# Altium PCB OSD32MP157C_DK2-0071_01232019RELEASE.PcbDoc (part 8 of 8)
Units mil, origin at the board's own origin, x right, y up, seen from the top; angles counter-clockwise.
Board outline 3976.38 x 2795.28 mil, 6 copper layers (Top Layer, Signal Layer 1, Signal Layer 2, Signal Layer 3, Signal Layer 4, Bottom Layer), stack 61.268 mil thick; 404 components, 418 nets, 1720 pads, 1233 vias.
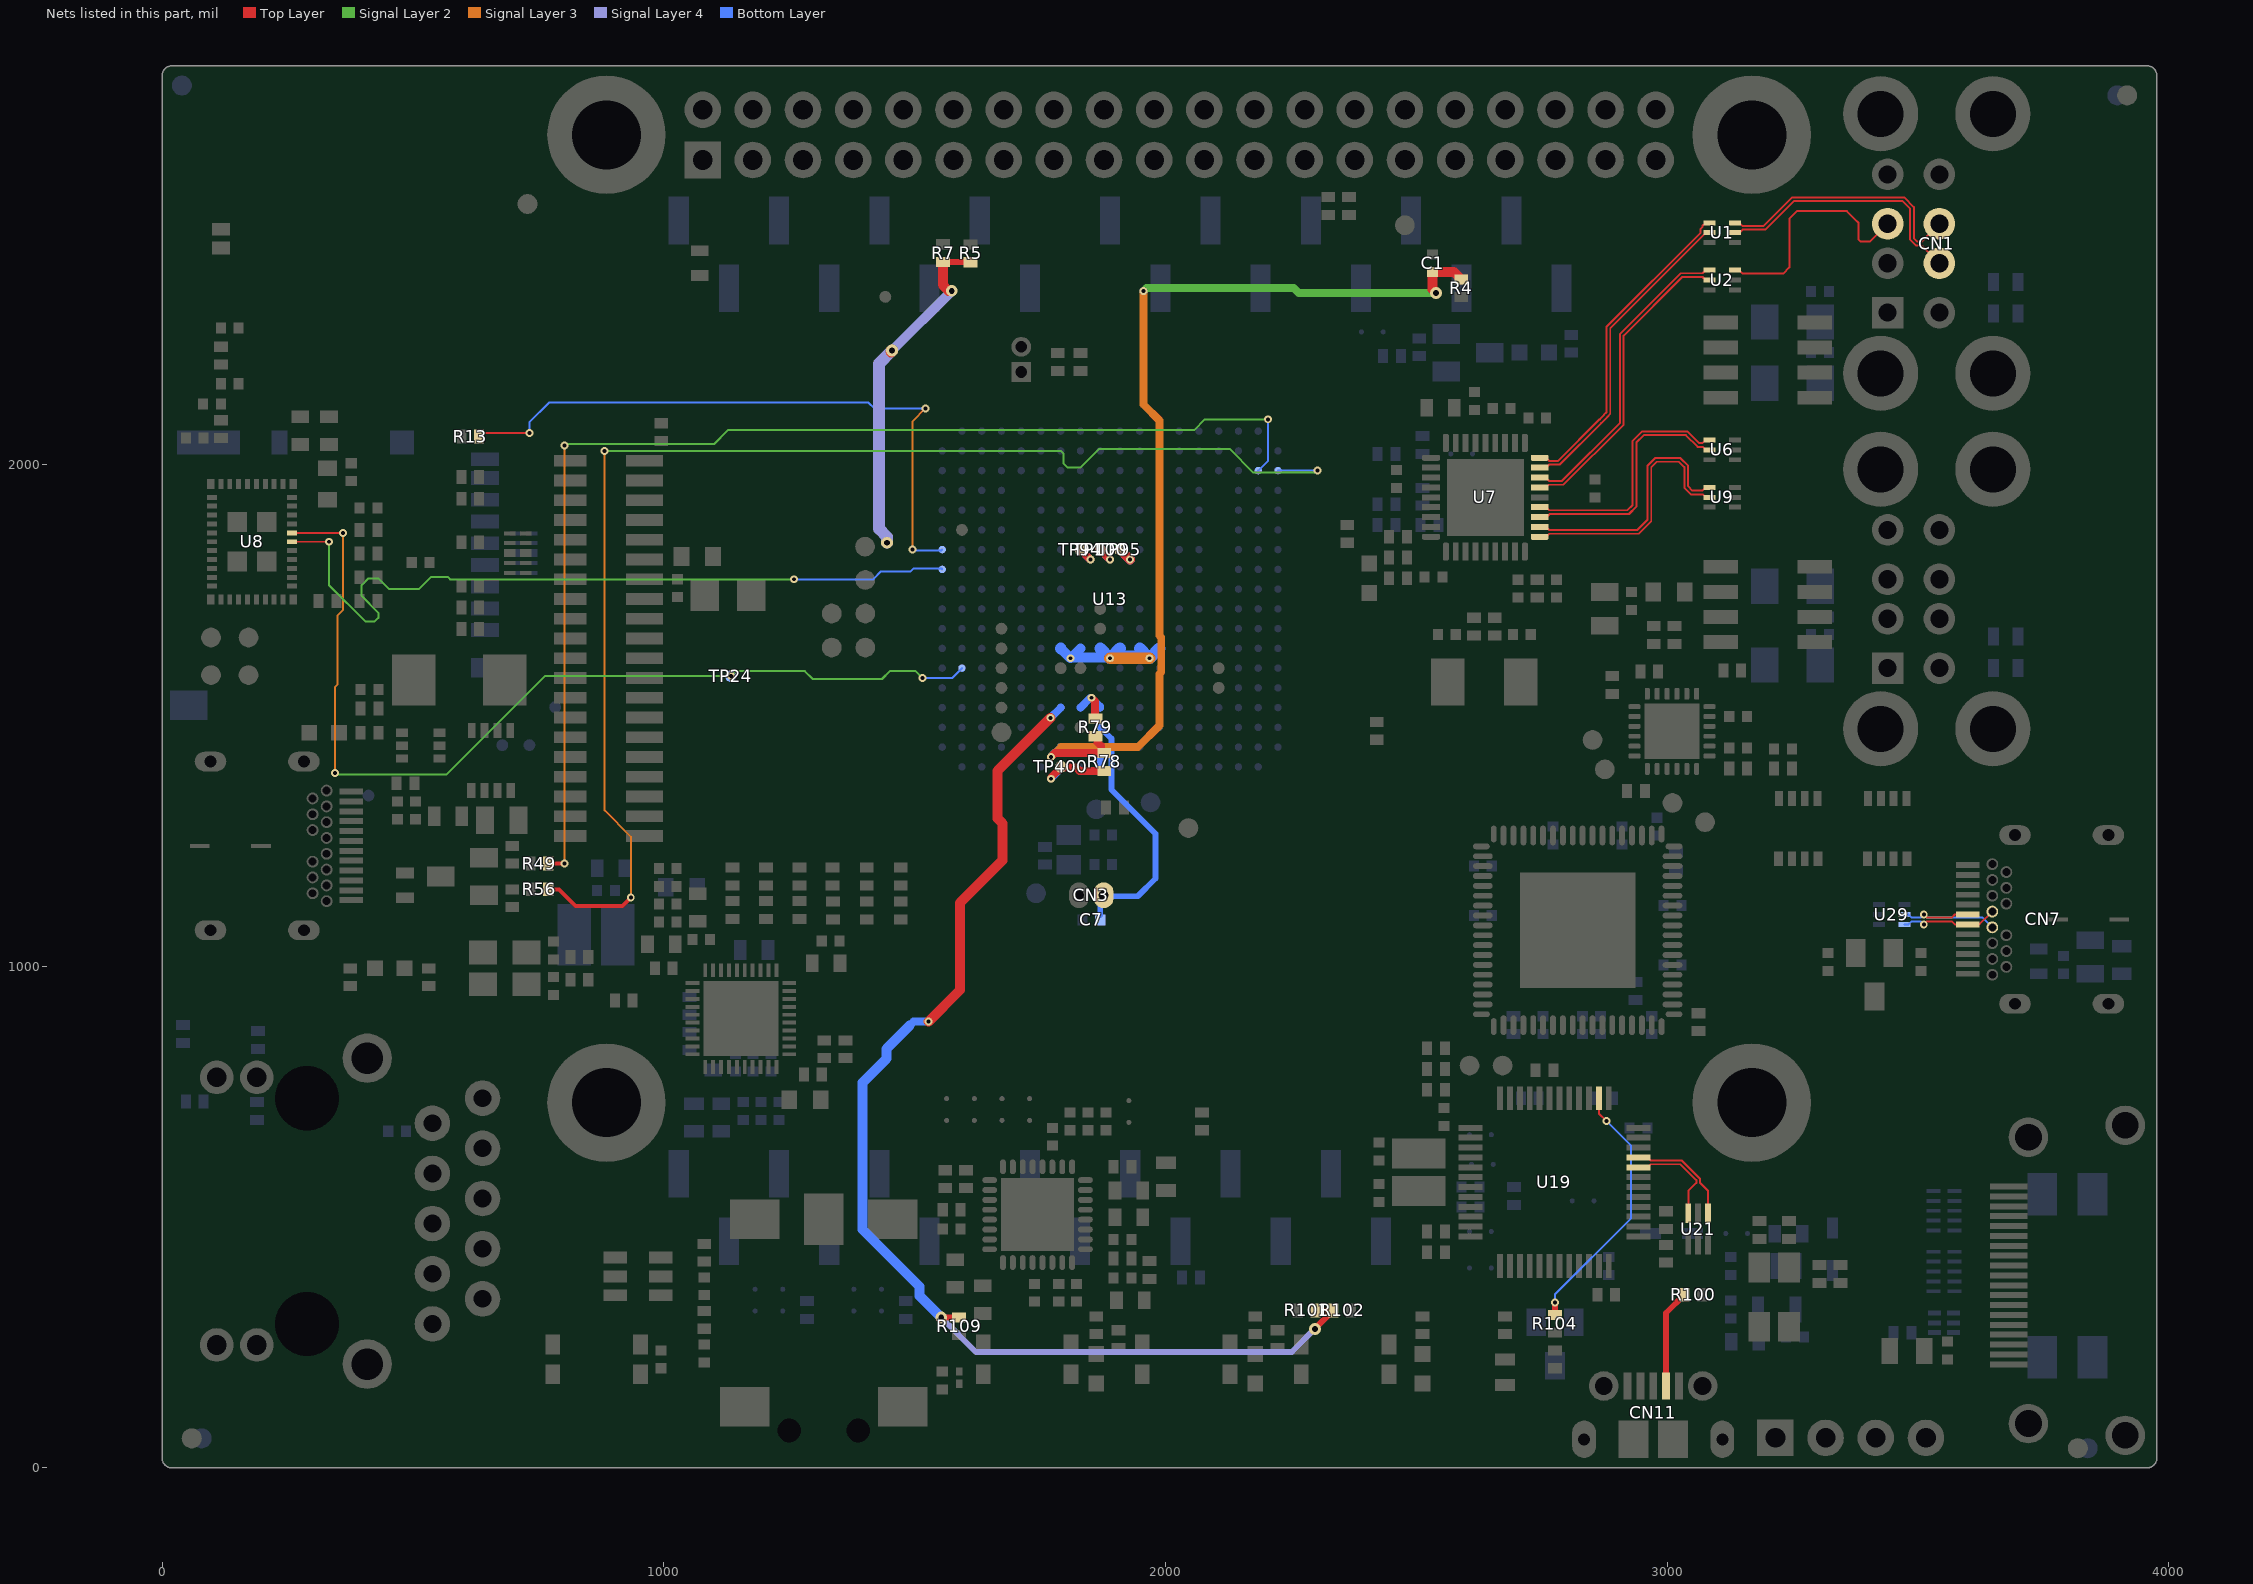
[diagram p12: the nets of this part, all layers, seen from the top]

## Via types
v1: diameter 15.75, hole 7.87, Top Layer to Bottom Layer, tented both sides, 803 vias
v2: diameter 23.62, hole 11.81, Top Layer to Bottom Layer, tented both sides, 417 vias
v3: diameter 15.75, hole 7.87, Top Layer to Bottom Layer, 13 vias

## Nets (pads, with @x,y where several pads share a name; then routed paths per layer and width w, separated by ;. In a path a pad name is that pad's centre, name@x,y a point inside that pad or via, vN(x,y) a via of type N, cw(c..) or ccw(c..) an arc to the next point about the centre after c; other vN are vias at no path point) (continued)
USB3CN26_P: CN1.T3 U2.6 | length 474.8
  Top Layer w3.94: U2.6@3135.83,2387.8 3143.7,2387.8 3150.59,2380.91 3231.3,2380.91 3243.92,2393.53 3243.92,2490.72 3258.71,2505.51 3358.41,2505.51 3379.31,2484.62 3381.5,2482.43 3381.5,2449.21 3386.02,2444.68 3404.13,2444.68 CN1.T3@3439.76,2480.31
USB4CN26_N: CN1.B2 U1.5 | length 520.8
  Top Layer w3.94: U1.5@3135.83,2462.6 3144.68,2462.6 3150.59,2468.5 3195.87,2468.5 3252.95,2525.59 3469.49,2525.59 3484.65,2510.43 3484.65,2448.48 3495.92,2437.2 3507.28,2437.2 CN1.B2@3542.91,2401.57
USB4CN26_P: CN1.B3 U1.6 | length 521
  Top Layer w3.94: U1.6@3135.83,2482.28 3143.7,2482.28 3150,2475.98 3192.77,2475.98 3249.85,2533.07 3472.59,2533.07 3492.13,2513.53 3492.13,2451.57 3499.02,2444.68 3507.28,2444.68 CN1.B3@3542.91,2480.31
USB_DCONN_N: CN7.A7 CN7.B7 U29.5 | length 283.1
  Top Layer w3.94: v1(3511.81,1103.35) 3517.91,1097.24 3567.52,1097.24 3573.62,1103.35 CN7.A7@3599.21,1103.35
  Bottom Layer w3.94: U29.5@3473.43,1103.35 3481.3,1103.35 3487.4,1097.24 3505.71,1097.24 v1(3511.81,1103.35) 3517.91,1097.24 3628.94,1097.24 CN7.B7@3648.43,1077.76
USB_DCONN_P: CN7.A6 CN7.B6 U29.6 | length 195.7
  Top Layer w3.94: v1(3511.81,1083.66) 3517.91,1089.76 3567.52,1089.76 3573.62,1083.66 CN7.A6@3599.21,1083.66 3622.83,1083.66 CN7.B6@3648.43,1109.25
  Bottom Layer w3.94: U29.6@3473.43,1083.66 3481.3,1083.66 3487.4,1089.76 3505.71,1089.76 v1(3511.81,1083.66)
USB_PWR_CC1: R49.2 U13.B16 | length 2400.8
  Top Layer w7.87: R49.2@769.68,1204.72 v1(802.17,1204.72)
  Signal Layer 2 w3.94: v1(802.17,2038.39) 805.12,2041.34 1100.39,2041.34 1127.95,2068.9 2057.09,2068.9 2078.74,2090.55 v1(2204.72,2090.55)
  Signal Layer 3 w3.94: v1(802.17,1204.72) v1(802.17,2038.39)
  Bottom Layer w3.94: U13.B16@2185.04,1988.19 2204.72,2007.87 v1(2204.72,2090.55)
USB_PWR_CC2: R56.2 U13.A16 | length 2662.9
  Top Layer w7.87: R56.2@769.68,1153.54 791.14,1153.54 824.02,1120.67 917.52,1120.67 v1(934.25,1137.4)
  Signal Layer 2 w3.94: v1(881.89,2027.56) 1169.09,2027.56 ; 1169.09,2027.56 1791.34,2027.56 1797.24,2021.65 1797.24,2002.17 1805.32,1994.09 1830.65,1994.09 1868.05,2031.5 2127.95,2031.5 2175.2,1984.25 2299.21,1984.25 v1(2303.15,1988.19)
  Signal Layer 3 w3.94: v1@881.89,2031.5 881.89,1311.02 934.25,1258.66 v1(934.25,1137.4)
  Bottom Layer w3.94: U13.A16@2224.41,1988.19 v1(2303.15,1988.19)
USB_RENUMN: R104.2 U19.38 | length 521.5
  Top Layer w3.94: U19.38@2864.17,737.2 2864.17,706.69 v1(2878.94,691.93)
  Top Layer w11.81: R104.2@2776.57,305.12 v1(2776.57,329.72)
  Bottom Layer w3.94: v1(2776.57,329.72) 2776.57,345.87 2928.35,497.64 2928.35,642.52 v1(2878.94,691.93)
USB_STLK_ID: CN11.4 R100.2 | length 197.2
  Top Layer w11.81: CN11.4@2998.03,163.39 2998.03,309.06 R100.2@3034.45,345.47
USB_STLK_N: U19.32 U21.6 | length 203.4
  Top Layer w3.94: U19.32@2942.91,599.41 2961.61,599.41 2967.72,605.51 3026.63,605.51 3058.27,573.87 3058.27,572.54 3058.27,569.89 3058.27,568.56 3042.32,552.61 U21.6@3042.32,508.07
USB_STLK_P: U19.33 U21.4 | length 215.8
  Top Layer w3.94: U19.33@2942.91,619.09 2961.61,619.09 2967.72,612.99 3029.72,612.99 3065.75,576.97 3065.75,568.56 3081.69,552.61 U21.4@3081.69,508.07
USBDN1_N: U7.1 U9.2 | length 517.3
  Top Layer w3.94: U7.1@2746.06,1856.3 2758.86,1856.3 2764.96,1862.4 2943.85,1862.4 2968.5,1887.06 2968.5,1995.08 2979.33,2005.91 3023.62,2005.91 3034.45,1995.08 3034.45,1953.99 3047.49,1940.94 3070.87,1940.94 3076.77,1935.04 U9.2@3084.65,1935.04
USBDN1_P: U7.2 U9.1 | length 517.4
  Top Layer w3.94: U7.2@2746.06,1875.98 2758.86,1875.98 2764.96,1869.88 2940.75,1869.88 2961.02,1890.16 2961.02,1998.18 2976.23,2013.39 3026.72,2013.39 3041.93,1998.18 3041.93,1957.09 3050.59,1948.43 3070.47,1948.43 3076.77,1954.72 U9.1@3084.65,1954.72
USBDN2_N: U6.2 U7.3 | length 493.3
  Top Layer w3.94: U7.3@2746.06,1895.67 2759.84,1895.67 2765.94,1901.77 2924.16,1901.77 2938.98,1916.59 2938.98,2044.29 2953.74,2059.06 3037.4,2059.06 3061.02,2035.43 3070.87,2035.43 3076.77,2029.53 U6.2@3084.65,2029.53
USBDN2_P: U6.1 U7.4 | length 493.5
  Top Layer w3.94: U7.4@2746.06,1915.35 2758.86,1915.35 2764.96,1909.25 2921.06,1909.25 2931.5,1919.69 2931.5,2047.39 2950.64,2066.54 3040.5,2066.54 3064.12,2042.91 3070.47,2042.91 3076.77,2049.21 U6.1@3084.65,2049.21
USBDN3_N: U2.2 U7.6 | length 618.6
  Top Layer w3.94: U7.6@2746.06,1954.72 2758.86,1954.72 2764.17,1960.04 2793.45,1960.04 2913.39,2079.97 2913.39,2257.14 3030.46,2374.21 3070.67,2374.21 3076.77,2368.11 U2.2@3084.65,2368.11
USBDN3_P: U2.1 U7.7 | length 619.3
  Top Layer w3.94: U7.7@2746.06,1974.41 2757.87,1974.41 2764.76,1967.52 2790.35,1967.52 2905.91,2083.07 2905.91,2260.24 3027.36,2381.69 3070.67,2381.69 3076.77,2387.8 U2.1@3084.65,2387.8
USBDN4_N: U1.2 U7.8 | length 632.8
  Top Layer w3.94: U7.8@2746.06,1994.09 2758.86,1994.09 2765.16,2000.39 2785.83,2000.39 2868.5,2083.07 2869.04,2083.07 2881.5,2095.52 2881.5,2096.06 2886.81,2101.38 2886.81,2271.9 3077.51,2462.6 U1.2@3084.65,2462.6
USBDN4_P: U1.1 U7.9 | length 643.5
  Top Layer w3.94: U7.9@2746.06,2013.78 2758.86,2013.78 2764.76,2007.87 2782.73,2007.87 2865.41,2090.55 2865.94,2090.55 2874.02,2098.62 2874.02,2099.16 2879.33,2104.48 2879.33,2275 3066.93,2462.6 3066.93,2469.97 3070.39,2473.43 3070.39,2475.9 3076.77,2482.28 U1.1@3084.65,2482.28
USD_DETECT: R13.1 U13.V12 | length 1288.3
  Top Layer w3.94: R13.1@631.89,2056.1 638.78,2062.99 v1(732.28,2062.99)
  Signal Layer 3 w3.94: v1(1496.06,1830.71) 1496.06,2086.61 v1(1521.65,2112.2)
  Bottom Layer w3.94: v1(732.28,2062.99) 732.28,2084.65 771.65,2124.02 1407.48,2124.02 1419.29,2112.2 v1(1521.65,2112.2) ; v1(1496.06,1830.71) 1498.03,1828.74 1553.15,1828.74 U13.V12@1555.12,1830.71
VBAT: C7.2 CN3.1 U13.K3 | length 507.9
  Bottom Layer w11.81: C7.2@1870.08,1102.36 1870.08,1134.84 CN3.1@1876.97,1141.73 1878.94,1139.76 1944.88,1139.76 1980.31,1175.2 1980.31,1264.32 1892.22,1352.41 1892.22,1454.23 U13.K3@1870.08,1476.38
VDD: R5.1 R7.1 R79.1 R101.2 R102.2 R109.2 U13.G7 U13.H7 U13.J7 U13.K4 U13.K7 U13.L4 U13.L7 U13.M4 U13.M7 | length 3576.9
  Top Layer w11.81: v2(1553.15,300.2) R109.2@1588.58,300.2 ; R7.1@1556.89,2404.13 R5.1@1611.02,2404.13 ; v2(2297.93,277.26) R102.2@2334.65,313.98 R101.2@2299.21,313.98
  Top Layer w15.75: v1(1852.36,1535.43) 1860.03,1527.76 1860.03,1494.46 R79.1@1860.39,1494.1
  Top Layer w19.68: R7.1@1556.89,2404.13 1556.89,2357.68 1567.92,2346.65 v2(1574.02,2346.65)
  Top Layer w20: v3(1527.56,889.76) 1590.55,952.76 1590.55,1126.63 1675.35,1211.44 1675.35,1285.03 1665.2,1295.19 1665.2,1389.76 1770.92,1495.49 v1(1771.08,1495.49)
  Top Layer w23.62: v2@1453.35,2225.98 v2(1454.72,2227.36)
  Signal Layer 3 w7.87: v2(1454.72,2227.36) 1454.72,2229.36 v2@1455.68,2230.31
  Signal Layer 3 w23.62: v1(1889.76,1614.17) v1(1968.5,1614.17)
  Signal Layer 4 w11.81: v2(1553.15,300.2) 1622.05,231.3 2251.97,231.3 v2(2297.93,277.26)
  Signal Layer 4 w19.68: v2@1454.63,2226.87 1454.63,2227.26 v2(1454.72,2227.36) v2(1574.02,2346.65)
  Signal Layer 4 w23.62: v2(1444.88,1844.49) 1444.88,1856.3 1429.13,1872.05 1429.13,2201.77 v2@1454.63,2227.26
  Bottom Layer w15.75: 1490.16,881.89 1498.03,889.76 v3(1527.56,889.76) ; v1(1771.08,1495.49) U13.M4@1791.34,1515.75 ; U13.L4@1830.71,1515.75 1850.39,1535.43 v1(1852.36,1535.43) 1870.08,1517.71 U13.K4@1870.08,1515.75
  Bottom Layer w19.68: U13.M7@1791.34,1633.86 v1(1811.02,1614.17) v1@1812.5,1615.65 ; U13.L7@1830.71,1633.86 v1@1812.5,1615.65 ; v1(1889.76,1614.17) 1888.29,1615.65 v1@1812.5,1615.65
  Bottom Layer w20: 1490.16,881.89 1443.9,835.63 1443.9,815.94 1395.98,768.03 1395.98,475.67 1510,361.66 1510,343.35 v2(1553.15,300.2)
  Bottom Layer w23.62: U13.K7@1870.08,1633.86 v1@1888.29,1615.65 ; v1(1889.76,1614.17) v1@1893.21,1617.62 ; U13.J7@1909.45,1633.86 v1@1893.21,1617.62 ; U13.H7@1948.82,1633.86 v1@1965.06,1617.62 ; U13.G7@1988.19,1633.86 v1(1968.5,1614.17) v1@1965.06,1617.62 ; v1@1893.21,1617.62 v1@1965.06,1617.62
VDD_DDR: TP100.1 U13.K12 | length 55.7
  Top Layer w15.75: TP100.1@1870.08,1830.71 v1(1889.76,1811.02)
  Bottom Layer w15.75: U13.K12@1870.08,1830.71 v1(1889.76,1811.02)
VDDA: R78.1 TP400.1 U13.M1 | length 150.9
  Top Layer w15.75: v1(1771.65,1374.01) 1771.65,1375.82 1791.96,1396.13 1822.53,1396.13 1828.89,1389.77 R78.1@1877.95,1389.77
  Bottom Layer w15.75: v1(1771.65,1374.01) 1791.34,1393.7 U13.M1@1791.34,1397.64
VREF+: C1.2 R4.2 R78.2 R79.2 U13.M2 | length 2012.8
  Top Layer w15.75: v1(1771.65,1417.32) 1779.53,1425.2 R78.2@1874.21,1425.2 ; R79.2@1862.56,1460.83 R79.2@1860.39,1458.67 1864.13,1458.67 1864.13,1446.89 1872.05,1438.98 1872.05,1427.37 R78.2@1874.21,1425.2 ; R78.2@1880.86,1424.12 R78.2@1877.95,1427.02 ; R78.2@1874.21,1425.2 R78.2@1875.45,1425.2 ; R78.2@1875.45,1425.2 1877.61,1427.37 R78.2@1877.95,1427.02 ; R78.2@1875.45,1425.2 R78.2@1877.95,1425.2 R78.2@1877.95,1427.02
  Top Layer w19.68: v2(2539.37,2342.52) 2532.48,2349.41 C1.2@2532.48,2383.86 2575.59,2383.86 R4.2@2589.92,2369.53
  Signal Layer 2 w15.75: v3(1956.69,2346.45) 1962.6,2352.36 2058.77,2352.36 ; 2058.77,2352.36 2075.08,2352.36 ; 2075.08,2352.36 2255.91,2352.36 2265.75,2342.52 v2(2539.37,2342.52)
  Signal Layer 3 w15.75: v1(1771.65,1417.32) 1791.34,1437.01 1944.88,1437.01 1988.19,1480.31 1988.19,1582.96 1991.73,1586.5 1991.73,1655.91 1988.19,1659.45 1988.19,2088.3 1956.69,2119.8 v3(1956.69,2346.45)
  Bottom Layer w15.75: v1(1771.65,1417.32) U13.M2@1791.34,1437.01
VREF_DDR: TP94.1 U13.L12 | length 55.7
  Top Layer w15.75: TP94.1@1830.71,1830.71 v1(1850.39,1811.02)
  Bottom Layer w15.75: U13.L12@1830.71,1830.71 v1(1850.39,1811.02)
VSSA: U13.K1 U13.K2 | length 39.4
  Bottom Layer w15.75: U13.K1@1870.08,1397.64 U13.K2@1870.08,1437.01
VTT_DDR: TP95.1 U13.J12 | length 55.7
  Top Layer w19.68: TP95.1@1909.45,1830.71 v1(1929.13,1811.02)
  Bottom Layer w19.68: U13.J12@1909.45,1830.71 v1(1929.13,1811.02)
WL_HOST_WAKE: U8.27 U13.V11 | length 1566.4
  Top Layer w3.94: U8.27@258.86,1846.46 v1(332.68,1846.46)
  Signal Layer 2 w3.94: v1(332.68,1846.46) 332.68,1759.84 405.51,1687.01 423.23,1687.01 431.1,1694.88 431.1,1704.84 397.67,1738.27 397.67,1759.88 411.42,1773.62 431.1,1773.62 452.76,1751.97 511.81,1751.97 536.42,1776.57 569.35,1776.57 574.27,1771.65 v1(1259.84,1771.65)
  Bottom Layer w3.94: v1(1259.84,1771.65) 1417.32,1771.65 1433.07,1787.4 1492.13,1787.4 1498.03,1793.31 1555.12,1793.31 U13.V11@1555.12,1791.34
WL_REG_ON: TP24.1 U8.28 U13.U6 | length 1949.6
  Top Layer w3.94: U8.28@258.86,1864.17 v1(360.24,1864.17)
  Signal Layer 2 w3.94: v1(344.49,1385.83) 347.44,1382.87 566.93,1382.87 762.8,1578.74 v1(1133.86,1578.74) 1143.7,1588.58 1281.5,1588.58 1297.24,1572.83 1435.04,1572.83 1450.79,1588.58 1501.97,1588.58 v1(1515.75,1574.8)
  Signal Layer 3 w3.94: v1(344.49,1385.83) 344.49,1556.55 349.41,1561.47 349.41,1699.27 360.24,1710.09 v1(360.24,1864.17)
  Bottom Layer w3.94: v1(1515.75,1574.8) 1574.8,1574.8 U13.U6@1594.49,1594.49
pads on no net: CN6.0 CN6.A2 CN6.A3 CN6.A6 CN6.A7 CN6.A8 CN6.A10 CN6.A11 CN6.B2 CN6.B3 CN6.B6 CN6.B7 CN6.B8 CN6.B10 CN6.B11 CN7.0 CN7.A2 CN7.A3 CN7.A8 CN7.A10 CN7.A11 CN7.B2 CN7.B3 CN7.B8 CN7.B10 CN7.B11 CN8.17 CN8.18 CN9.14 CN10.NPTH1 CN10.NPTH2 CN16.1 CN16.8 L1.2 U1.4 U2.4 U6.4 U8.13 U8.15 U8.16 U9.4 U10.4 U10.5 U10.6 U10.7 U12.16 U12.17 U12.19 U13.D7 U13.D8 U13.D9 U13.D10 U13.G8 U13.H12 U13.M16 U13.P9 U13.P10 U13.R9 U13.R10 U14.36 U14.37 U14.38 U14.39 U14.40 U19.4 U19.11 U19.14 U19.16 U19.17 U19.19 U19.21 U19.22 U19.28 U19.29 U19.40 U19.41 U19.42 U19.43 U19.45 U19.46 U20.19 U20.20 U20.23 U20.24 U29.4 U33.5 X2.2 X2.4
copper on no net: | length 33.5
  Bottom Layer w11.81: v2(2990.16,705.71) 2990.16,739.17
  other v2: 1043.31,2256.89 1043.31,2315.94

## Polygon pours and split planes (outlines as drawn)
GND on Bottom Layer "GND_L06_P130" (solid, remove dead copper, pour order 130): 89.45,2820.55 1752.83,2820.55 2301.65,2820.55 4065.83,2820.55 4065.83,25.28 89.45,25.28
GND on Bottom Layer "GND_L06_P134" (solid, remove dead copper, pour order 134): 1604.33,2795.28 1604.33,2312.99 2340.06,2312.99 2340.06,2795.28
NetC69_2 on Bottom Layer "NETC69_2_L06_P097" (solid, remove dead copper, pour order 97): 319.88,1300.2 311.81,1292.12 311.81,1186.23 322.11,1175.91 539.1,1175.91 556.1,1192.91 556.1,1288.39 544.29,1300.2
3V3 on Signal Layer 4 "3V3_L05_P113" (solid, remove dead copper, pour order 113): 1952.12,2635.43 1934.06,2617.37 1934.06,2570.87 1916.34,2553.15 1839.57,2553.15 1817.91,2574.8 1817.91,2624.2 1806.68,2635.43 1146.62,2635.43 1134.8,2621.62 1134.8,2566.88 1117.13,2549.21 1011.42,2549.21 859.45,2397.24 859.45,2212.2 977.56,2094.09 977.56,2074.41 967.72,2064.57 957.87,2064.57 898.82,2005.51 898.82,1966.54 583.86,1651.57 583.86,1533.07 524.8,1474.02 416.54,1474.02 396.85,1454.33 396.85,1414.96 485.43,1326.38 652.76,1326.38 731.5,1405.12 826.77,1405.12 1066.14,1644.49 1066.14,1769.29 1125.2,1828.35 1125.2,1867.72 1144.88,1887.4 1144.88,1926.77 1135.04,1936.61 1095.67,1936.61 1085.83,1946.46 1085.83,1966.14 1095.67,1975.98 2224.41,1975.98 2224.41,598.61 1115.35,598.03 997.24,479.92 997.24,283.07 1026.77,253.54 1479.53,253.54 1538.58,194.49 1853.54,194.49 1873.23,174.8 2335.83,174.8 2365.35,204.33 2365.35,322.44 2375.2,332.28 2493.31,332.28 2522.83,302.76 2522.83,26.77 2496.06,0 3.15,0 3.15,1705.71 381.69,2084.25 603.54,2084.25 633.07,2113.78 633.07,2743.7 682.28,2792.91 3034.65,2792.91 3034.65,2694.49 3005.12,2664.96 2847.64,2664.96 2818.11,2635.43
GND on Signal Layer 4 "GND_L05_P144" (solid, remove dead copper, pour order 144): 1308.87,1023.62 2401.57,1023.62 2401.57,2422.42 1308.87,2422.43
3V3 on Signal Layer 4 "3V3_L05_P117" (solid, remove dead copper, pour order 117): 2881.53,2409.06 2936.22,2354.37 2936.22,1641.34 2562.21,1267.32 2562.2,991.73 2601.57,952.36 2601.57,706.3 2601.57,499.61 2522.83,420.87 2460.63,420.87 2460.63,342.13 2483.46,342.13 2493.31,332.28 2463.78,302.76 2385.63,302.76 2375.45,292.58 2365.69,292.58 2355.51,302.76 2325.98,302.76 2266.93,243.7 1935.04,243.7 1925.2,253.54 1824.02,253.54 1814.17,263.39 1814.17,308.07 1828.54,322.44 1961.81,322.44 1971.65,312.6 2011.02,312.6 2020.87,322.44 2020.87,607.87 1892.91,735.83 1873.23,735.83 1863.39,745.67 1863.39,785.04 1873.23,794.88 2208.07,794.88 2227.56,775.39 2227.56,735.83 2247.24,716.14 2365.35,716.14 2385.04,735.83 2385.04,863.78 2385.04,942.52 2375.2,952.36 2296.46,1031.1 2296.46,1139.37 2424.41,1267.32 2424.41,2369.69 2463.78,2409.06
AGND on Signal Layer 4 "AGND_L05_P109" (solid, remove dead copper, pour order 109): 1135.04,578.35 1016.93,460.24 1016.93,291.14 1034.84,273.23 1429.72,273.23 1504.53,348.03 1542.52,348.03 1614.96,275.59 1782.68,275.59 1804.33,297.24 1804.33,321.85 1814.76,332.28 1964.57,332.28 1974.41,322.44 2001.18,322.44 2011.02,332.28 2011.02,603.15 1891.73,722.44 1613.78,722.44 1607.48,716.14 1607.48,647.24 1538.58,578.35
5V_VIN on Signal Layer 4 "5V_VIN_L05_P090" (solid, remove dead copper, pour order 90): 2263.78,1338.58 2263.78,1484.8 1940.4,1484.8 1940.4,1338.58
5V_VIN on Signal Layer 4 "5V_VIN_L05_P112" (solid, remove dead copper, pour order 112): 2878.35,2428.74 2958.66,2348.43 2989.17,2348.43 3024.61,2383.86 3024.61,2625.79 3005.42,2644.97 2893.7,2645.28 2857.48,2645.28 2827.95,2615.75 1952.76,2615.75 1940.06,2602.46 1940.06,2567.03 1919.29,2546.26 1834.65,2546.26 1810.65,2570.26 1810.65,2598.41 1793.31,2615.75 1282.48,2615.75 1260.83,2637.8 1233.46,2637.8 1233.46,2723.23 1223.43,2733.27 1068.9,2733.27 1047.24,2711.61 1047.24,2644.98 1056.4,2635.83 1118.11,2635.83 1140.95,2612.99 1140.95,2573.04 1105.51,2537.6 1027.36,2537.6 879.13,2389.37 879.13,2202.36 987.4,2094.09 987.4,2074.41 918.5,2005.51 918.5,1956.3 603.54,1641.34 603.54,1530.51 527.36,1454.33 426.38,1454.33 416.54,1444.49 416.54,1424.8 495.28,1346.06 642.91,1346.06 721.65,1424.8 820.08,1424.8 1047.24,1651.97 1047.24,1770.08 1115.35,1838.19 1115.35,1877.56 1125.2,1887.4 1125.2,1916.93 1115.35,1926.77 1085.83,1926.77 1066.14,1946.46 1066.14,1973.43 1088.39,1995.67 1233.46,1995.67 1294.88,1995.67 1294.88,2192.52 1294.88,2362.2 1361.42,2428.74
5V_VIN on Signal Layer 4 "5V_VIN_L05_P142" (solid, remove dead copper, pour order 142): 1732.28,2244.09 1850.39,2244.09 1850.39,2450.79 1732.28,2450.79
GND on Signal Layer 4 "GND_L05_P118" (solid, remove dead copper, pour order 118): 2098.03,1267.32 2098.03,1266.84 2084.84,1253.65 2084.84,1245.4 2171.19,1159.06 2296.46,1159.06 2355.51,1218.11 2355.51,1257.48 2345.67,1267.32
5V_VIN on Signal Layer 4 "5V_VIN_L05_P091" (solid, remove dead copper, pour order 91): 2086.61,1338.58 2263.78,1338.58 2263.78,2451.59 2086.61,2451.59
GND on Signal Layer 4 "GND_L05_P120" (solid, remove dead copper, pour order 120): 2709.84,1385.43 2591.73,1267.32 2591.73,995.87 2621.26,966.34 2621.26,696.46 2621.26,588.19 2680.31,529.13 2680.31,460.24 2729.53,411.02 2916.54,411.02 2936.22,430.71 2986.32,430.71 2995.28,439.67 2995.28,784.25 3123.23,912.2 3123.23,1237.8 2975.59,1385.43
5V_VIN on Signal Layer 4 "5V_VIN_L05_P119" (solid, remove dead copper, pour order 119): 3010.04,435.63 3010.04,770.28 3142.91,903.15 3142.91,1237.8 2975.59,1405.12 2818.11,1405.12 2798.43,1424.8 2798.43,1470.98 2946.06,1618.62 2946.06,2615.75 2965.75,2635.43 3014.96,2635.43 3036.22,2614.17 3036.22,2584.65 3123.23,2497.64 3280.71,2497.64 3329.92,2448.43 3329.92,1418.14 3516.93,1231.13 3516.93,996.85 3615.35,898.43 3615.35,24.8 3590.55,0 2565.94,0 2542.52,23.42 2542.52,302.76 2493.31,351.97 2464.57,351.97 2464.57,411.02 2985.43,411.02
GND on Signal Layer 4 "GND_L05_P123" (solid, remove dead copper, pour order 123): 3044.49,2783.07 3044.49,2605.91 3133.07,2517.32 3290.55,2517.32 3349.61,2458.27 3349.61,1424.8 3536.61,1237.8 3536.61,1001.57 3635.04,903.15 3635.04,20.47 3655.51,0 3969.68,0 3969.68,2783.07
NetC69_2 on Signal Layer 4 "NETC69_2_L05_P095" (solid, remove dead copper, pour order 95): 359.25,1299.21 354.33,1294.29 354.33,1187.99 364.17,1178.15 451.77,1178.15 506.99,1233.37 544.39,1233.37 555.12,1244.09 555.12,1263.78 549.21,1269.69 444.88,1269.69 415.34,1299.23 394.9,1299.23
GND on Signal Layer 4 "GND_L05_P110" (solid, remove dead copper, pour order 110): 3.15,1749.61 32.45,1749.61 383.24,2100.39 590.16,2100.39 613.39,2123.62 613.39,2792.91 3.15,2792.91
GND on Signal Layer 3 "GND_L04_P146" (solid, remove dead copper, pour order 146): -1.62,2795.49 3973.77,2795.49 3973.77,0.21 -1.62,0.21
GND on Signal Layer 3 "GND_L04_P128" (solid, remove dead copper, pour order 128): 2433.98,198.74 2234.24,198.83 2234.27,0.01 3976.38,0 3976.38,2795.28 3090.55,2795.28 3061.02,2765.75 3061.02,2135.83 3001.97,2076.77 2530.77,2076.77 2509.84,2097.7 2509.84,2165.35 2549.21,2204.72 2627.95,2204.72 2864.17,2440.94 2864.17,2509.84 2874.02,2519.69 2874.02,2795.28 1614.17,2795.28 1614.17,1673.23 1663.39,1624.02 1968.51,1624.01 1968.51,1486.22 2116.14,1338.58 2116.14,1123.62 1985.71,993.2 1763.3,993.2 1400.79,1355.71 1400.79,2795.27 0,2795.28 0,118.11 2234.25,118.11 2234.25,561.02 2283.46,610.24 2283.46,768.6 2312.11,797.24 2462.6,797.24 2492.13,767.72 2492.13,256.89
VDD on Signal Layer 3 "VDD_L04_P124" (solid, remove dead copper, pour order 124): 1909.45,1625.84 1641.88,1625.84 1479.53,1788.19 1479.53,1843.31 1458.69,1864.14 1431.07,1864.15 1400.79,1833.86 1400.79,1748.82 1759.84,1389.77 1909.45,1539.37
NetC69_2 on Signal Layer 3 "NETC69_2_L04_P094" (solid, remove dead copper, pour order 94): 333.66,1301.18 327.95,1295.47 327.95,1184.84 332.68,1180.12 529.53,1180.12 548.13,1198.72 548.13,1284.55 531.5,1301.18
GND on Signal Layer 2 "GND_L03_P126" (solid, remove dead copper, pour order 126): 0,2795.28 3976.38,2795.28 3976.38,0 0,0
NetC69_2 on Signal Layer 2 "NETC69_2_L03_P100" (solid, remove dead copper, pour order 100): 382.35,1302.23 335.69,1302.23 323.03,1289.57 323.03,1192.72 335.63,1180.12 524.61,1180.12 548.13,1203.64 548.13,1283.57 529.53,1302.17
GND on Top Layer "GND_L01_P104" (solid, remove dead copper, pour order 104): 19.69,-97.71 4071.76,-97.71 4071.76,2775.59 19.68,2775.59
NetC69_2 on Top Layer "NETC69_2_L01_P096" (solid, remove dead copper, pour order 96): 464.57,1320.87 440.94,1297.24 440.94,1179.13 451.77,1168.31 502.95,1168.31 505.91,1171.26 505.91,1201.46 556.1,1251.66 556.1,1320.87
5V_VIN on Top Layer "5V_VIN_L01_P102" (solid, remove dead copper, pour order 102): 649.61,1625.98 649.3,1626.29 605.62,1626.29 598.43,1619.09 598.43,1479.33 625.98,1451.77 705.71,1451.77 730.31,1476.38 730.31,1625.98
5V_VIN on Top Layer "5V_VIN_L01_P101" (solid, remove dead copper, pour order 101): 421.26,1482.28 415.29,1476.31 415.29,1404.59 424.28,1395.6 464.73,1395.6 487.2,1418.07 487.2,1437.01 502.95,1452.76 502.95,1476.38 497.05,1482.28
NetC71_2 on Top Layer "NETC71_2_L01_P093" (solid, remove dead copper, pour order 93): 540.75,1432.09 533.46,1424.8 533.46,1389.76 536.42,1386.81 551.18,1386.81 571.85,1366.14 571.85,1266.73 580.71,1257.87 673.23,1257.87 687.01,1271.65 687.01,1317.91 694.88,1325.79 709.65,1325.79 731.3,1347.44 731.3,1424.21 723.43,1432.09
NetC66_2 on Top Layer "NETC66_2_L01_P098" (solid, remove dead copper, pour order 98): 3233.27,1454.72 3227.56,1449.02 3227.56,1327.56 3239.17,1315.94 3489.17,1315.94 3497.05,1323.82 3497.05,1442.91 3485.24,1454.72
5V_VIN on Top Layer "5V_VIN" (solid, remove dead copper, pour order 92): 1019.68,2527.56 1019.68,2734.25 1047.24,2761.81 1206.69,2761.81 1232.28,2736.22 1232.28,2675.2 1207.68,2650.59 1145.67,2650.59 1137.8,2642.72 1137.8,2535.43 1108.27,2505.91 1041.34,2505.91
GND on Signal Layer 1 "GND_L02_P105" (solid, remove dead copper, pour order 105): 0,2795.28 3975.39,2795.28 3975.39,0 0,0

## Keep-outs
Keep-Out Layer:
  rectangle: 282.48,35.43 617.13,104.33

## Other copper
Top Layer:
  region: 103.35,2766.73 103.35,2463.58 125,2463.58 125,2766.73
  rectangle: 103.35,2745.08 538.39,2766.73
  pour cut-out: 2602.36,1708.66 2561.22,1667.52 2561.22,1645.86 2525.59,1610.24 2525.59,1516.54 2526.38,1515.75 2746.06,1515.75 2746.06,1614.18 2710.63,1649.61 2710.63,1669.29 2671.26,1708.66
  pour cut-out: 761.61,1055.59 608.27,1055.59 608.27,937.01 610.24,935.04 846.46,935.04 866.14,954.72 866.14,1027.56 850.39,1043.31 773.9,1043.31
  pour cut-out: 1913.88,579.82 1923.72,569.98 1994.13,569.98 2002,562.11 2002,320.9 1976.17,295.07 1897.85,295.07 1854.82,338.09 1854.82,579.41 1832.01,579.41 1810.53,600.89 1810.53,637.3 1835.14,661.91 1913.88,661.91
  pour cut-out: 2573.62,866.14 2573.62,834.84 2616.14,792.32 2616.14,754.92 2592.52,731.3 2546.26,731.3 2539.37,738.19 2539.37,801.55 2529.53,811.39 2522.27,811.39 2518.46,807.58 2498.33,807.58 2482.48,823.43 2482.48,836.81 2511.81,866.14
  pour cut-out: 2411.42,561.02 2421.26,551.18 2590.55,551.18 2590.55,618.11 2578.74,629.92 2411.42,629.92
  text "1" at 292.32,45.28 h78.74
Signal Layer 1:
  text "2" at 341.54,45.28 h78.74
Signal Layer 2:
  text "3" at 400.59,45.28 h78.74
Signal Layer 3:
  text "4" at 489.17,45.28 h78.74
Signal Layer 4:
  text "5" at 548.23,45.28 h78.74
Bottom Layer:
  pour cut-out: 1854.34,1172.24 1868.14,1186.04 1868.14,1272.64 1852.38,1288.4 1795.32,1288.4 1779.53,1272.6 1779.53,1188.03 1795.31,1172.24
  text "6" at 607.28,45.28 h78.74
Multi-Layer:
  pour cut-out: -1.48,2795.28 -1.48,2396.65 560.53,2396.65 560.53,2795.28

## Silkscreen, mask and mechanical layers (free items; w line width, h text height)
Top Overlay:
  drawing of 484 lines, arcs and shapes, not listed
  text "OSD32MP157C-DK2-0071-EA" at 53.15,2704.72 h39.37
  text "GPIO" at 2752.95,2500 h66.93
  text "USB" at 3746.06,2123.03 h66.93
  text "GND" at 1503.94,1874.02 h47.24
  text "DSI" at 1013.78,1528.54 h66.93
  text "PWR_IN" at 25.59,1444.88 h66.93
  text "USB" at 3743.11,1412.4 h66.93
  text "USB" at 3743.11,865.16 h66.93
  text "HDMI" at 3743.11,718.5 h66.93
  text "AUDIO" at 1199.8,623.03 h66.93
  text "ST-LINK" at 2850.39,258.86 h66.93
  text "ETHERNET" at 44.29,150.59 h66.93
  text "USER2" at 2256.89,53.15 h66.93
  text "RESET" at 1636.81,51.18 h66.93
  text "USER1" at 1952.76,51.18 h66.93
  text "PWR ON" at 742.13,50.2 h66.93
Bottom Overlay:
  region: 1362.08,1714.17 1362.08,1950.39 1342.39,1950.39 1342.39,1714.17
  region: 1007.75,1714.17 1007.75,1950.39 988.06,1950.39 988.06,1714.17
  region: 1362.02,1733.87 1007.69,1733.87 1007.69,1714.18 1362.02,1714.18
  region: 1362.02,1950.4 1007.69,1950.4 1007.69,1930.72 1362.02,1930.72
  region: 1131.89,1611.22 1175.2,1617.13 1221.46,1611.22 1271.65,1583.66 1311.02,1542.32 1326.77,1499.02 1330.71,1450.79 1322.83,1402.56 1290.35,1348.43 1256.89,1320.87 1256.89,1379.92 1033.46,1379.92 1008.86,1453.74 1050.2,1453.74 1071.85,1434.06 1105.31,1438.98 1118.11,1454.72 1133.86,1452.76 1139.76,1423.23 1153.54,1408.46 1186.02,1405.51 1207.68,1421.26 1214.57,1450.79 1203.74,1473.43 1207.68,1480.31 1221.46,1484.25 1252.95,1518.7 1256.89,1559.06 1237.2,1571.85 1204.72,1576.77 1190.94,1566.93 1173.23,1575.79 1166.34,1569.88 1160.43,1571.85 1152.56,1593.5
  region: 1259.84,1340.55 1089.57,1340.55 1089.57,1386.81 1031.5,1386.81 1050.2,1355.31 1082.68,1325.79 1140.75,1301.18 1180.12,1297.24 1226.38,1307.09 1261.81,1324.8
  region: 1077.76,1588.58 1084.65,1583.66 1076.77,1557.09 1085.63,1526.57 1090.55,1517.72 1087.6,1514.76 1070.87,1512.8 1050.2,1497.05 1044.29,1467.52 1051.18,1449.8 1014.76,1449.8 1013.78,1484.25 1032.48,1539.37 1061.02,1573.82 1078.74,1589.57
  lines w4.72: 1141.73,649.61 1147.64,643.7 1226.38,643.7 1248.03,665.35 ; 1248.03,750.98 1282.48,785.43 1437.99,785.43 ; 3114.17,361.22 3147.64,361.22
  lines w7.87: 1574.8,21.65 1574.8,218.5 2559.06,218.5 2559.06,21.65 1968.5,21.65 1574.8,21.65
  lines w10: 1077.76,1587.6 ccw(c1172.97,1458.96) 1129.26,1612.92 ; 1084.61,1584.3 ccw(c1134,1555.84) 1092.52,1516.73 ; 1090.66,1513.48 ccw(c1083.97,1474.68) 1120.28,1459.45 ; 1121.06,1459.65 1126.76,1453.95 ; 1125.98,1453.74 1135.55,1453.74 ; 1128.98,1608.85 cw(c1115.87,1566.26) 1158.46,1553.15 ; 1135.28,1454.45 ccw(c1173.56,1445.28) 1203.19,1471.2 ; 1158.35,1553.15 1172.24,1577.76 ; 1173.23,1577.76 1186.02,1571.85 ; 1174.21,1547.79 cw(c1217.26,1529.02) 1254.92,1557.09 ; 1174.21,1548.23 1187.87,1570.99 ; 1201.77,1473.43 cw(c1207.52,1473.59) 1207.35,1479.34 ; 1209.65,1480.31 ccw(c1187.66,1545.2) 1255.24,1556.43
  text "OSD32MP157C-DK2-0071-EB" at 551.18,2696.85 h39.37
  text "D10" at 2016.73,2476.38 h66.93 r270
  text "D0" at 956.69,2475.39 h66.93 r270
  text "D2" at 1156.5,2475.39 h66.93 r270
  text "D4" at 1354.33,2475.39 h66.93 r270
  text "D6" at 1556.1,2475.39 h66.93 r270
  text "D8" at 1818.9,2475.39 h66.93 r270
  text "GND" at 2415.35,2475.39 h59.06 r270
  text "D14" at 2616.14,2475.39 h66.93 r270
  text "D12" at 2216.54,2474.41 h66.93 r270
  text "AVDD" at 2567.91,2323.82 h59.06
  text "D11" at 2162.4,2320.87 h66.93
  text "D13" at 2363.19,2319.88 h66.93
  text "D7" at 1682.09,2318.9 h66.93
  text "D9" at 1958.66,2318.9 h66.93
  text "D15" at 2763.78,2318.9 h66.93
  text "D3" at 1301.18,2315.94 h66.93
  text "D1" at 1097.44,2313.98 h66.93
  text "D5" at 1457.68,2292.32 h66.93 r270
  text "RoHS" at 1291.14,1851.97 h62.99
  text "COMPLIANT" at 1306.89,1796.85 h31.5
  text "2002/95/EC" at 1326.57,1745.67 h31.5
  text "MICRO SD CARD" at 555.99,1440.94 h66.93
  text "STM32" at 1259.84,1336.61 h59.06
  text "BOOT0" at 3760.83,609.25 h66.93 r270
  text "BOOT2" at 3824.8,608.27 h66.93 r270
  text "3V3" at 2157.48,576.77 h66.93 r270
  text "IOREF" at 2261.81,576.77 h66.93 r270
  text "GND" at 1957.68,575.79 h66.93 r270
  text "A5" at 1057.09,574.8 h66.93 r270
  text "A3" at 1257.87,574.8 h66.93 r270
  text "VIN" at 1758.86,574.8 h66.93 r270
  text "A1" at 1457.68,573.82 h66.93 r270
  text "A2" at 1358.27,394.69 h66.93 r270
  text "A4" at 1158.46,392.72 h66.93 r270
  text "A0" at 1556.1,392.72 h66.93 r270
  text "5V" at 2061.02,392.72 h66.93 r270
  text "GND" at 1860.24,337.6 h66.93 r270
  text "NRST" at 2258.86,303.15 h66.93 r270
  text "IO" at 3492.13,129.92 h66.93 r270
  text "GND" at 3396.65,119.09 h66.93 r270
  text "3V3" at 3195.87,113.98 h66.93 r270
  text "TCK" at 3296.26,113.98 h66.93 r270
  text ".Layer_Name" at 1291.34,-1580.71 h118.11
  text ".GBO" at 2446.85,-2011.81 h118.11
Top Paste:
  text ".Layer_Name" at 557.1,-1602.36 h118.11
  text ".GTP" at 2198.62,-1602.36 h118.11
Top Solder:
  rectangle: 282.48,35.43 617.13,104.33
  text ".Layer_Name" at 557.1,-1602.36 h118.11
Bottom Solder:
  rectangle: 282.48,35.43 617.13,104.33
M1-Board Shape:
  the board outline again, w3.94
M14-Top Assembly:
  text ".Layer_Name" at 557.1,-1602.36 h118.11
  text ".GM14" at 2198.62,-1602.36 h118.11
Drill Drawing:
  drawing of 541 lines, arcs and shapes, not listed
  text "PCB SPECIFICATIONS :" at 272.44,6849.02 h118.11
  text "**Plating type :" at 4880.71,6835.24 h98.43
  text "PCB : TYPE 4" at 6113.24,6835.14 h118.11
  text "A.   MATERIAL :" at 272.44,6691.54 h118.11
  text "FR-4" at 1788.19,6691.54 h118.11
  text "TG-170" at 2437.8,6691.54 h118.11
  text "X  TG-150" at 3156.3,6691.54 h118.11
  text "TG-140" at 3786.22,6691.54 h118.11
  text "lead Gold" at 5145.47,6659.05 h98.43
  text "ASPECT-RATIO, AXE Z :" at 6113.24,6618.6 h118.11
  text "B.   MATERIAL FAMILY :" at 272.44,6573.42 h118.11
  text "N/A" at 1788.19,6573.42 h118.11
  text "X   RED" at 3165.35,6460.63 h118.11
  text "C.   SOLDERMASK COLOR :" at 272.44,6455.31 h118.11
  text "WHITE" at 2437.8,6455.31 h118.11
  text "BLACK" at 3786.22,6455.31 h118.11
  text "GREEN" at 1826.77,6452.76 h118.11
  text "6:1 to 8:1 / LEVEL \"B\"" at 6113.98,6352.95 h118.11
  text "D.   SILKSCREEN COLOR :" at 272.44,6337.2 h118.11
  text "X  WHITE" at 1788.19,6337.2 h118.11
  text "YELLOW" at 2437.8,6337.2 h118.11
  text "BLACK" at 3156.3,6337.2 h118.11
  text "Blue ink PANTONE 2955" at 3786.22,6337.2 h118.11
  text "E.   SURFACE FINISH :" at 272.44,6219.09 h118.11
  text "X  ENIG" at 1788.19,6219.09 h118.11
  text "IMMERSION SILVER" at 2437.8,6219.09 h118.11
  text "IMMERSION TIN" at 3786.22,6219.09 h118.11
  text "HASL" at 1788.19,6100.98 h118.11
  text "HASL (PB-FREE)" at 2437.8,6100.98 h118.11
  text "GOLDEN FINGER" at 3786.22,6100.98 h118.11
  text "MINIMUN PARAMETERS" at 6110.04,6072.44 h118.11
  text "F.   IMPEDANCE CONTROL :" at 272.44,5982.87 h118.11
  text "NO" at 1788.19,5982.87 h118.11
  text "X  YES  (SEE IMPEDANCE TABLE FOR DETAIL INFORMATION)" at 2437.8,5982.87 h118.11
  text "G.   THROUGH VIA :" at 272.44,5864.76 h118.11
  text "PLUG THE VIAS WHICH ARE COVERED WITH SOLDERMASK ONE OR TWO SIDE." at 1788.19,5864.76 h118.11
  text "DEFAULT" at 6110.04,5855.91 h118.11
  text "PLUG MATERIAL :" at 1788.19,5746.65 h118.11
  text "X  SOLDERMASK" at 2792.13,5746.65 h118.11
  text "NON-CONDUCTIVE EPOXY." at 3786.22,5746.65 h118.11
  text "TRACKS : 0.090mm           / GAPS : 0.090mm" at 6110.04,5629.53 h118.11
  text "H.   STACK-UP :" at 272.44,5628.54 h118.11
  text "SEE LAYER STACK-UP SEQUENCE FOR OVERALL THICKNESS." at 1788.19,5628.54 h118.11
  text "Layer" at 6193.77,5200.79 h78.74
  text "Name" at 6523.17,5200.79 h78.74
  text "Material" at 7160.04,5200.79 h78.74
  text "Thickness" at 7800.45,5200.79 h78.74
  text "Constant" at 8270.56,5200.79 h78.74
  text "Board Layer Stack" at 8705.84,5200.79 h78.74
  text "IMPEDANCE TABLE     SDMMC1" at 2493.11,5195.87 h118.11
  text "Top Overlay" at 6523.17,5043.31 h78.74
  text "LAYER" at 2660.43,4999.02 h118.11
  text "TRACE" at 3300.2,4999.02 h118.11
  text "SPACING" at 3713.58,4999.02 h118.11
  text "IMPEDANCE" at 4245.08,4999.02 h118.11
  text "IMPEDANCE" at 4914.37,4999.02 h118.11
  text "TOL." at 5652.56,4999.02 h118.11
  text "(mm)" at 3844.49,4901.57 h98.43
  text "(mm)" at 3378.94,4899.61 h98.43
  text "(Single ended)" at 4264.76,4890.75 h98.43
  text "(Differential)" at 4963.58,4890.75 h98.43
  text "Top Solder" at 6523.17,4885.83 h78.74
  text "Solder Resist" at 7160.04,4885.83 h78.74
  text "0.020mm" at 7800.45,4885.83 h78.74
  text "3.5" at 8270.56,4885.83 h78.74
  text "+/- 7R" at 5615.35,4747.44 h118.11
  text "0.130" at 3338.58,4744.09 h118.11
  text "0.260" at 3812.01,4743.11 h118.11
  text "TOP/BOTTOM" at 2512.01,4742.52 h118.11
  text "50 ohm" at 4377.17,4740.55 h118.11
  text "NA" at 5146.85,4738.58 h118.11
  text "1" at 6193.77,4728.35 h78.74
  text "Top Layer" at 6523.17,4728.35 h78.74
  text "Copper" at 7160.04,4728.35 h78.74
  text "0.037mm" at 7800.45,4728.35 h78.74
  text "+/- 7R" at 5615.55,4609.06 h118.11
  text "0.130" at 3338.78,4605.71 h118.11
  text "0.260" at 3812.2,4604.72 h118.11
  text "COUCHE 3" at 2588.58,4603.35 h118.11
  text "50 ohm" at 4377.36,4602.17 h118.11
  text "NA" at 5147.05,4600.2 h118.11
  text "Dielectric 1" at 6523.17,4570.87 h78.74
  text "IT-180A 3313H" at 7160.04,4570.87 h78.74
  text "0.099mm" at 7800.45,4570.87 h78.74
  text "4.2" at 8270.56,4570.87 h78.74
  text "2" at 6193.69,4413.39 h78.74
  text "Signal Layer 1" at 6523.17,4413.39 h78.74
  text "Copper" at 7160.04,4413.39 h78.74
  text "0.035mm" at 7800.45,4413.39 h78.74
  text "IMPEDANCE TABLE     USB" at 2487.2,4325.79 h118.11
  text "Dielectric 2" at 6523.17,4255.91 h78.74
  text "IT-180A" at 7160.04,4255.91 h78.74
  text "0.130mm" at 7800.45,4255.91 h78.74
  text "4.2" at 8270.56,4255.91 h78.74
  text "LAYER" at 2654.53,4128.94 h118.11
  text "TRACE" at 3294.29,4128.94 h118.11
  text "SPACING" at 3707.68,4128.94 h118.11
  text "IMPEDANCE" at 4239.17,4128.94 h118.11
  text "IMPEDANCE" at 4908.46,4128.94 h118.11
  text "TOL." at 5646.65,4128.94 h118.11
  text "3" at 6193.77,4098.43 h78.74
  text "Signal Layer 2" at 6523.17,4098.43 h78.74
  text "Copper" at 7160.04,4098.43 h78.74
  text "0.035mm" at 7800.45,4098.43 h78.74
  text "(mm)" at 3838.58,4031.5 h98.43
  text "(mm)" at 3373.03,4029.53 h98.43
  text "(Single ended)" at 4258.86,4020.67 h98.43
  text "(Differential)" at 4957.68,4020.67 h98.43
  text "Dielectric 3" at 6523.17,3940.95 h78.74
  text "IT-180A 1080*2" at 7160.04,3940.95 h78.74
  text "0.885mm" at 7800.45,3940.95 h78.74
  text "4.25" at 8270.56,3940.95 h78.74
  text "0.100" at 3332.68,3874.02 h118.11
  text "NA" at 4459.65,3874.02 h118.11
  text "0.090" at 3806.1,3873.03 h118.11
  text "90 ohm" at 5036.42,3873.03 h118.11
  text "+/- 13R" at 5587.6,3873.03 h118.11
  text "TOP/BOTTOM" at 2506.1,3872.44 h118.11
  text "4" at 6193.77,3783.46 h78.74
  text "Signal Layer 3" at 6523.17,3783.46 h78.74
  text "Copper" at 7160.04,3783.46 h78.74
  text "0.035mm" at 7800.45,3783.46 h78.74
  text "IMPEDANCE TABLE     DSI" at 2487.2,3640.75 h118.11
  text "Dielectric 4" at 6523.17,3625.98 h78.74
  text "IT-180A" at 7160.04,3625.98 h78.74
  text "0.130mm" at 7800.45,3625.98 h78.74
  text "4.2" at 8270.56,3625.98 h78.74
  text "5" at 6193.77,3468.5 h78.74
  text "Signal Layer 4" at 6523.17,3468.5 h78.74
  text "Copper" at 7160.04,3468.5 h78.74
  text "0.035mm" at 7800.45,3468.5 h78.74
  text "LAYER" at 2654.53,3443.9 h118.11
  text "TRACE" at 3294.29,3443.9 h118.11
  text "SPACING" at 3707.68,3443.9 h118.11
  text "IMPEDANCE" at 4239.17,3443.9 h118.11
  text "IMPEDANCE" at 4908.46,3443.9 h118.11
  text "TOL." at 5646.65,3443.9 h118.11
  text "(mm)" at 3838.58,3346.46 h98.43
  text "(mm)" at 3373.03,3344.49 h98.43
  text "(Single ended)" at 4258.86,3335.63 h98.43
  text "(Differential)" at 4957.68,3335.63 h98.43
  text "Dielectric 5" at 6523.17,3311.02 h78.74
  text "IT-180A 3313H" at 7160.04,3311.02 h78.74
  text "0.099mm" at 7800.45,3311.02 h78.74
  text "4.2" at 8270.56,3311.02 h78.74
  text "0.100" at 3332.68,3188.98 h118.11
  text "NA" at 4459.65,3188.98 h118.11
  text "0.130" at 3806.1,3187.99 h118.11
  text "100 ohm" at 5036.42,3187.99 h118.11
  text "+/- 15R" at 5587.6,3187.99 h118.11
  text "TOP/BOTTOM" at 2506.1,3187.4 h118.11
  text "6" at 6193.77,3153.54 h78.74
  text "Bottom Layer" at 6523.17,3153.54 h78.74
  text "Copper" at 7160.04,3153.54 h78.74
  text "0.037mm" at 7800.45,3153.54 h78.74
  text "Bottom Solder" at 6523.17,2996.06 h78.74
  text "Solder Resist" at 7160.04,2996.06 h78.74
  text "0.020mm" at 7800.45,2996.06 h78.74
  text "3.5" at 8270.56,2996.06 h78.74
  text "Symbol" at 4518.47,2840.5 h94.49
  text "Count" at 4888.12,2840.5 h94.49
  text "Hole Size" at 5306.07,2840.5 h94.49
  text "Plated" at 6063.56,2840.5 h94.49
  text "Hole Type" at 6388.1,2840.5 h94.49
  text "Drill Layer Pair" at 6860.35,2840.5 h94.49
  text "Hole Length" at 7755.81,2840.5 h94.49
  text "Routed Path Length" at 8469.47,2840.5 h94.49
  text "Bottom Overlay" at 6523.17,2838.58 h78.74
  text "816" at 4888.12,2677.5 h78.74
  text "0.200mm (7.87mil)" at 5306.07,2677.5 h78.74
  text "PTH" at 6063.56,2677.5 h78.74
  text "Round" at 6388.1,2677.5 h78.74
  text "Top Layer - Bottom Layer" at 6860.35,2677.5 h78.74
  text "-" at 7755.81,2677.5 h78.74
  text "-" at 8469.47,2677.5 h78.74
  text "417" at 4888.12,2514.5 h78.74
  text "0.300mm (11.81mil)" at 5306.07,2514.5 h78.74
  text "PTH" at 6063.56,2514.5 h78.74
  text "Round" at 6388.1,2514.5 h78.74
  text "Top Layer - Bottom Layer" at 6860.35,2514.5 h78.74
  text "-" at 7755.81,2514.5 h78.74
  text "-" at 8469.47,2514.5 h78.74
  text "28" at 4888.12,2351.5 h78.74
  text "0.400mm (15.75mil)" at 5306.07,2351.5 h78.74
  text "PTH" at 6063.56,2351.5 h78.74
  text "Round" at 6388.1,2351.5 h78.74
  text "Top Layer - Bottom Layer" at 6860.35,2351.5 h78.74
  text "-" at 7755.81,2351.5 h78.74
  text "-" at 8469.47,2351.5 h78.74
  text "I" at 4499.52,2341.51 h72.44
  text "2" at 4888.12,2188.5 h78.74
  text "0.500mm (19.69mil)" at 5306.07,2188.5 h78.74
  text "PTH" at 6063.56,2188.5 h78.74
  text "Round" at 6388.1,2188.5 h78.74
  text "Top Layer - Bottom Layer" at 6860.35,2188.5 h78.74
  text "-" at 7755.81,2188.5 h78.74
  text "-" at 8469.47,2188.5 h78.74
  text "J" at 4487.45,2178.51 h72.44
  text "2" at 4888.12,2025.5 h78.74
  text "0.600mm (23.62mil)" at 5306.07,2025.5 h78.74
  text "PTH" at 6063.56,2025.5 h78.74
  text "Round" at 6388.1,2025.5 h78.74
  text "Top Layer - Bottom Layer" at 6860.35,2025.5 h78.74
  text "-" at 7755.81,2025.5 h78.74
  text "-" at 8469.47,2025.5 h78.74
  text "8" at 4888.12,1862.5 h78.74
  text "0.600mm (23.62mil)" at 5306.07,1862.5 h78.74
  text "PTH" at 6063.56,1862.5 h78.74
  text "Slot" at 6388.1,1862.5 h78.74
  text "Top Layer - Bottom Layer" at 6860.35,1862.5 h78.74
  text "1.200mm (47.24mil)" at 7755.81,1862.5 h78.74
  text "0.600mm (23.62mil)" at 8469.47,1862.5 h78.74
  text "H" at 4487.45,1852.51 h72.44
  text "2" at 4888.12,1699.5 h78.74
  text "0.600mm (23.62mil)" at 5306.07,1699.5 h78.74
  text "PTH" at 6063.56,1699.5 h78.74
  text "Slot" at 6388.1,1699.5 h78.74
  text "Top Layer - Bottom Layer" at 6860.35,1699.5 h78.74
  text "1.300mm (51.18mil)" at 7755.81,1699.5 h78.74
  text "0.700mm (27.56mil)" at 8469.47,1699.5 h78.74
  text "A" at 4487.45,1689.51 h72.44
  text "12" at 4888.12,1536.5 h78.74
  text "0.900mm (35.43mil)" at 5306.07,1536.5 h78.74
  text "PTH" at 6063.56,1536.5 h78.74
  text "Round" at 6388.1,1536.5 h78.74
  text "Top Layer - Bottom Layer" at 6860.35,1536.5 h78.74
  text "-" at 7755.81,1536.5 h78.74
  text "-" at 8469.47,1536.5 h78.74
  text "16" at 4888.12,1373.49 h78.74
  text "0.920mm (36.22mil)" at 5306.07,1373.49 h78.74
  text "PTH" at 6063.56,1373.49 h78.74
  text "Round" at 6388.1,1373.49 h78.74
  text "Top Layer - Bottom Layer" at 6860.35,1373.49 h78.74
  text "-" at 7755.81,1373.49 h78.74
  text "-" at 8469.47,1373.49 h78.74
  text "F" at 4487.45,1363.51 h72.44
  text "48" at 4888.12,1210.49 h78.74
  text "1.000mm (39.37mil)" at 5306.07,1210.49 h78.74
  text "PTH" at 6063.56,1210.49 h78.74
  text "Round" at 6388.1,1210.49 h78.74
  text "Top Layer - Bottom Layer" at 6860.35,1210.49 h78.74
  text "-" at 7755.81,1210.49 h78.74
  text "-" at 8469.47,1210.49 h78.74
  text "2" at 4888.12,1047.49 h78.74
  text "1.200mm (47.24mil)" at 5306.07,1047.49 h78.74
  text "NPTH" at 6063.56,1047.49 h78.74
  text "Round" at 6388.1,1047.49 h78.74
  text "Top Layer - Bottom Layer" at 6860.35,1047.49 h78.74
  text "-" at 7755.81,1047.49 h78.74
  text "-" at 8469.47,1047.49 h78.74
  text "4" at 4888.12,884.49 h78.74
  text "1.350mm (53.15mil)" at 5306.07,884.49 h78.74
  text "PTH" at 6063.56,884.49 h78.74
  text "Round" at 6388.1,884.49 h78.74
  text "Top Layer - Bottom Layer" at 6860.35,884.49 h78.74
  text "-" at 7755.81,884.49 h78.74
  text "-" at 8469.47,884.49 h78.74
  text "K" at 4487.45,874.5 h72.44
  text "2" at 4888.12,721.49 h78.74
  text "1.600mm (62.99mil)" at 5306.07,721.49 h78.74
  text "PTH" at 6063.56,721.49 h78.74
  text "Round" at 6388.1,721.49 h78.74
  text "Top Layer - Bottom Layer" at 6860.35,721.49 h78.74
  text "-" at 7755.81,721.49 h78.74
  text "-" at 8469.47,721.49 h78.74
  text "8" at 4888.12,558.49 h78.74
  text "2.330mm (91.73mil)" at 5306.07,558.49 h78.74
  text "PTH" at 6063.56,558.49 h78.74
  text "Round" at 6388.1,558.49 h78.74
  text "Top Layer - Bottom Layer" at 6860.35,558.49 h78.74
  text "-" at 7755.81,558.49 h78.74
  text "-" at 8469.47,558.49 h78.74
  text "G" at 4487.45,548.5 h72.44
  text "2" at 4888.12,395.49 h78.74
  text "3.250mm (127.95mil)" at 5306.07,395.49 h78.74
  text "NPTH" at 6063.56,395.49 h78.74
  text "Round" at 6388.1,395.49 h78.74
  text "Top Layer - Bottom Layer" at 6860.35,395.49 h78.74
  text "-" at 7755.81,395.49 h78.74
  text "-" at 8469.47,395.49 h78.74
  text "4" at 4888.12,232.49 h78.74
  text "3.500mm (137.79mil)" at 5306.07,232.49 h78.74
  text "PTH" at 6063.56,232.49 h78.74
  text "Round" at 6388.1,232.49 h78.74
  text "Top Layer - Bottom Layer" at 6860.35,232.49 h78.74
  text "-" at 7755.81,232.49 h78.74
  text "-" at 8469.47,232.49 h78.74
  text "N" at 4487.45,222.5 h72.44
  text "1373 Total" at 4888.12,69.49 h78.74
  text "Slot definitions :" at 4518.47,-44.61 h78.74
  text "Routed Path Length" at 5055.24,-44.61 h78.74
  text "= Calculated from tool start centre position to tool end centre position." at 5720.22,-44.61 h78.74
  text "Hole Length" at 5055.24,-109.81 h78.74
  text "= Routed Path Length + Tool Size = Slot length as defined in the PCB layout" at 5473.4,-109.81 h78.74
M20-Top Sheet Box:
  circle w10: c324.84,-1855.81 r51.18
  lines w11.81: 1380.63,-2051.85 1380.63,-1264.45 ; 1380.63,-1855 3742.83,-1855 ; 1380.63,-1658.15 3742.83,-1658.15 ; 1380.63,-1461.3 3742.83,-1461.3 ; 2168.03,-2051.85 2168.03,-1461.3 ; 199.53,-2051.85 199.53,-1264.45 3742.83,-1264.45 3742.83,-2051.85 199.53,-2051.85
  text "Project: OSD32MP15x DK2 Reference Design" at 1413.39,-1401.57 h118.11
  text "Date: 10-OCT-19" at 2200.79,-1600.39 h118.11
  text "Rev: C-01" at 1411.42,-1602.36 h118.11
  text "Octavo Systems LLC" at 314.96,-1688.98 h118.11
  text "R" at 305.12,-1883.86 h60
M21-Bottom Sheet Box:
  circle w10: c324.84,-932.58 r51.18
  lines w11.81: 1380.63,-1128.62 1380.63,-341.22 ; 1380.63,-931.77 3742.83,-931.77 ; 1380.63,-734.92 3742.83,-734.92 ; 1380.63,-538.07 3742.83,-538.07 ; 2168.03,-1128.62 2168.03,-538.07 ; 199.53,-1128.62 3742.83,-1128.62 3742.83,-341.22 199.53,-341.22 199.53,-1128.62
  text "Project: OSD32MP15x DK2 Reference Design" at 3695.83,-467.83 h118.11
  text "Date: 10-OCT-19" at 3690.94,-688.98 h118.11
  text "Rev: C-01" at 2125.98,-696.85 h118.11
  text "Octavo Systems LLC" at 1299.21,-785.43 h118.11
  text "R" at 344.84,-962.58 h60

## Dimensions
19.68,2795.28 to 19.68,0 on M2-Board Dimensions
0,2775.59 to 3976.38,2775.59 on M2-Board Dimensions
